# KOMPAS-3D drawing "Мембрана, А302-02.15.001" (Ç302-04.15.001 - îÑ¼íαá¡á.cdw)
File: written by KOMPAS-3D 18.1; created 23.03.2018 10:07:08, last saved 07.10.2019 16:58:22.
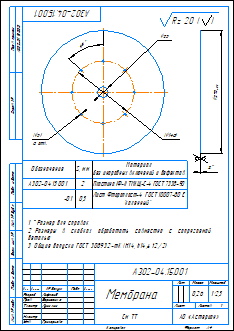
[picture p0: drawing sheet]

Sheet 1: A4, portrait

Document properties: Автор: Милов; Организация: Милов; Полное имя файла: D:\Мембранные насосы\Мембранный электропривод\А302-00.00.000 - ASTRA-302 (МЭ200)\А302-04.00.000 - Мембранный насос ASTRA-302-PP\А302-04.15.001 - Мембрана.cdw; Масса: 0.264223; Параметр неуказанной шероховатости: Rz 20

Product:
- Part/product: Мембрана  | designation А302-02.15.001
    Масса: 0.264223
    Раздел спецификации: Детали
    Форматы листов документа: A4
- Part/product: Мембрана  | designation А302-01.15.001
    Масса: 0.266387
    Раздел спецификации: Детали
    Форматы листов документа: A4
    source file: ..\3Д ПВХ\А302-01.15.001 - Мембрана.cdw
- Part/product: Мембрана  | designation А302-04.15.001
    Масса: 0.264223
    Раздел спецификации: Детали
    Форматы листов документа: A4

Title block, sheet 1: Наименование: Мембрана; designation: А302-04.15.001; Масса: 0,26; scale: 1:2,5; Количество листов документа: 1; organisation: АО «Астерион»; Форматы листов документа: A4; stored path: \\192.168.87.28\Konstructor_doc\Мембранные насосы\Мембранный электропривод\А302-00.00.000 - ASTRA-302 (МЭ200)\Чертежи\А302-00.15.001 - Мембрана.cdw; Разработал: Лифлянд; Проверил: Борисенко; Т. контр.: Лучихин; Утвердил: Григорьева

Views: Вид 1, Спереди, Проекционный вид 2
Referenced files in Z:\Мембранные насосы\Мембранный электропривод\А302-00.00.000 - ASTRA-302 (МЭ200)\3Д\: А302-00.15.001 - Мембрана.m3d
Referenced files in D:\Мембранные насосы\Мембранный электропривод\А302-00.00.000 - ASTRA-302 (МЭ200)\3Д ПВХ\: А302-01.15.001 - Мембрана.m3d
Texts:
  См. ТТ
  S, мм
  без инородных включений и дефектов
  Лист Фторопласт-4  ГОСТ 10007-80 Е
  "каленный"
  Пластина ІФ-IІ ТМКЩ-C-4 ГОСТ 7338-90
  Rz 20
  Rz 20 ( )
Dimensions and other numbers on the sheet: 5; 8 отв.; 25; 140; 278; -01; 0,5; 2; 1:2,5; 1; 0,26

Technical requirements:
  *Размер для справок.
  Размеры в скобках обработать совместно с сопрягаемой
  деталью.
  Общие допуски ГОСТ 30893.2-mK (H14, h14,  t2/2).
